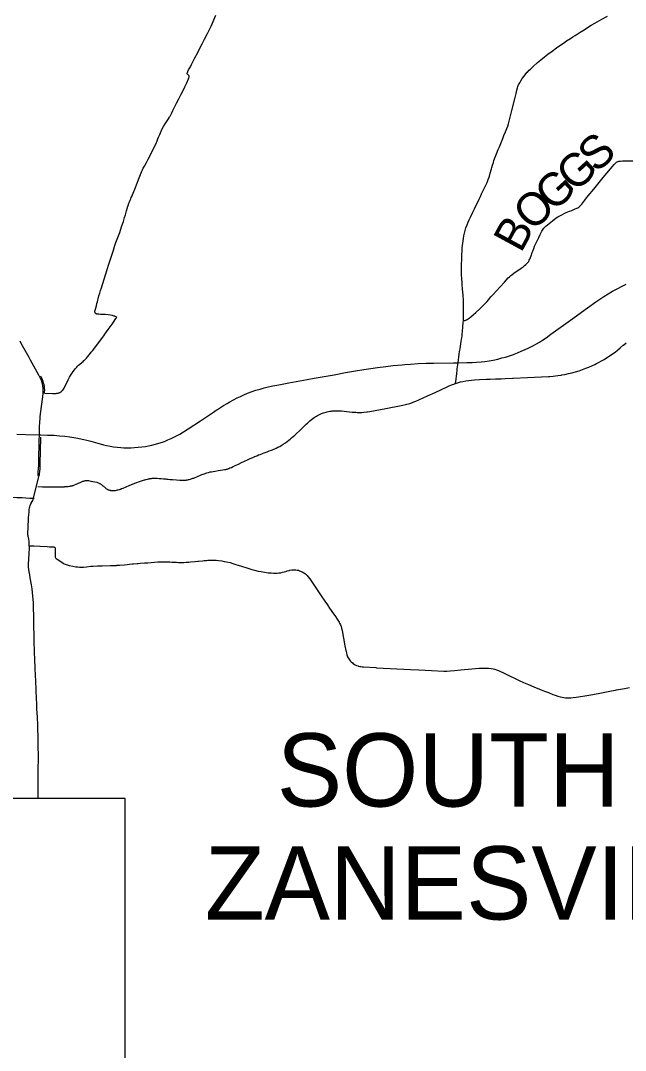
# Model space of a CAD drawing. Extents: x 1761803 to 2441803, y 509895 to 949895.
# Drawn here: x 2107842 to 2124353, y 786865 to 814988 of the extents above; entities that cross this region are included whole.
import ezdxf

# ---------------------------------------------------------------- set-up
doc = ezdxf.new("R2010")
doc.units = 0
for name, color, linetype in [('GM_X_County_Road', 7, 'Continuous'), ('GM_X_Minor_Lake', 7, 'Continuous'), ('GM_X_Minor_River', 7, 'Continuous'), ('GM_X_Minor_River_Text', 7, 'Continuous'), ('GM_X_State_Location', 7, 'Continuous')]:
    doc.layers.add(name, color=color, linetype=linetype)

msp = doc.modelspace()

# ---------------------------------------------------------------- linework, layer by layer
at = {"layer": 'GM_X_County_Road'}
for points in [[(2123340, 810199), (2123493, 810385), (2123751, 810703), (2124047, 811054), (2124099, 811111), (2124113, 811122), (2124127, 811131), (2124143, 811138), (2124158, 811143), (2124173, 811147), (2124189, 811150), (2124221, 811153), (2124270, 811156), (2124434, 811156), (2124926, 811161), (2125171, 811164), (2125433, 811164), (2125586, 811166)], [(2121823, 808691), (2121852, 808763), (2121875, 808824), (2121901, 808884), (2121931, 808952), (2121987, 809060), (2122030, 809149), (2122071, 809238), (2122087, 809266), (2122105, 809293), (2122125, 809318), (2122148, 809341), (2122185, 809374), (2122362, 809520), (2122466, 809598), (2122506, 809625), (2122562, 809658), (2122620, 809687), (2122679, 809716), (2122738, 809743), (2122828, 809782), (2122888, 809806), (2122964, 809837), (2123025, 809864), (2123054, 809879), (2123082, 809897), (2123103, 809912), (2123120, 809929), (2123146, 809955), (2123163, 809975), (2123189, 810009), (2123244, 810081), (2123296, 810145), (2123340, 810199)], [(2121505, 808228), (2121559, 808266), (2121601, 808296), (2121637, 808326), (2121672, 808360), (2121694, 808386), (2121713, 808412), (2121728, 808442), (2121742, 808472), (2121760, 808518), (2121778, 808564), (2121812, 808656), (2121823, 808691)], [(2119930, 806796), (2119956, 806799), (2119978, 806802), (2119984, 806804), (2120000, 806809), (2120016, 806816), (2120030, 806824), (2120059, 806841), (2120085, 806860), (2120137, 806901), (2120206, 806960), (2120274, 807019), (2120381, 807119), (2120576, 807317), (2120620, 807366), (2120684, 807441), (2120735, 807503), (2120835, 807609), (2120937, 807716), (2121053, 807846), (2121157, 807959), (2121191, 807994), (2121227, 808027), (2121252, 808048), (2121304, 808086), (2121505, 808228)]]:
    msp.add_lwpolyline(points, dxfattribs=at)
at = {"layer": 'GM_X_Minor_Lake'}
for points in [[(2112327, 813175), (2112381, 813289), (2112426, 813395), (2112437, 813426), (2112441, 813443), (2112443, 813460), (2112443, 813472), (2112441, 813481), (2112435, 813490), (2112427, 813498), (2112416, 813505), (2112405, 813515), (2112395, 813525), (2112390, 813534), (2112389, 813542), (2112390, 813552), (2112395, 813567), (2112407, 813596), (2112430, 813640), (2112476, 813727), (2112506, 813785), (2112602, 813975), (2112677, 814120), (2112744, 814252), (2112797, 814353), (2112866, 814483), (2112941, 814632), (2113007, 814760), (2113045, 814840), (2113176, 815132)], [(2121958, 813840), (2122042, 813912), (2122143, 813996), (2122235, 814067), (2122355, 814156), (2122474, 814244), (2122595, 814330), (2122662, 814375), (2122743, 814431), (2122853, 814502), (2122915, 814541), (2122978, 814581), (2123116, 814669), (2123227, 814740), (2123350, 814820), (2123420, 814864), (2123519, 814922), (2123706, 815024), (2123850, 815101), (2123866, 815110)], [(2120695, 810936), (2120707, 810975), (2120724, 811036), (2120748, 811115), (2120764, 811165), (2120794, 811256), (2120831, 811347), (2120880, 811469), (2120912, 811544), (2120931, 811590), (2120949, 811635), (2121004, 811772), (2121036, 811847), (2121081, 811952), (2121118, 812043), (2121140, 812105), (2121160, 812167), (2121183, 812246), (2121256, 812532), (2121332, 812849), (2121368, 812996), (2121391, 813090), (2121407, 813149), (2121417, 813184), (2121427, 813211), (2121439, 813235), (2121468, 813290), (2121502, 813346), (2121537, 813403), (2121586, 813470), (2121636, 813533), (2121676, 813580), (2121679, 813583), (2121724, 813632), (2121759, 813666), (2121832, 813733), (2121958, 813840)], [(2111923, 812379), (2111943, 812416), (2111969, 812470), (2111997, 812529), (2112100, 812733), (2112162, 812849), (2112230, 812980), (2112318, 813156), (2112327, 813175)], [(2111275, 811112), (2111323, 811201), (2111440, 811428), (2111499, 811546), (2111541, 811636), (2111571, 811703), (2111593, 811762), (2111608, 811803), (2111639, 811879), (2111678, 811969), (2111707, 812028), (2111746, 812099), (2111789, 812169), (2111861, 812279), (2111906, 812348), (2111918, 812370), (2111923, 812379)], [(2111133, 810828), (2111153, 810876), (2111171, 810915), (2111191, 810956), (2111221, 811013), (2111275, 811112)], [(2110764, 809895), (2110778, 809936), (2110801, 809999), (2110819, 810043), (2110836, 810087), (2110850, 810119), (2110865, 810156), (2110884, 810203), (2110895, 810230), (2110977, 810428), (2111007, 810505), (2111076, 810690), (2111133, 810828)], [(2119848, 806086), (2119862, 806174), (2119879, 806281), (2119887, 806329), (2119895, 806380), (2119896, 806388), (2119900, 806422), (2119908, 806497), (2119919, 806626), (2119927, 806741), (2119930, 806796), (2119934, 806844), (2119936, 806934), (2119938, 806986), (2119938, 807045), (2119938, 807113), (2119936, 807212), (2119930, 807344), (2119920, 807488), (2119907, 807656), (2119899, 807783), (2119893, 807867), (2119890, 807908), (2119880, 808071), (2119878, 808101), (2119876, 808156), (2119875, 808242), (2119877, 808342), (2119884, 808456), (2119892, 808607), (2119896, 808685), (2119898, 808733), (2119901, 808785), (2119905, 808844), (2119912, 808906), (2119921, 808970), (2119930, 809035), (2119946, 809114), (2119961, 809181), (2119982, 809260), (2120001, 809324), (2120034, 809415), (2120061, 809481), (2120091, 809547), (2120127, 809624), (2120191, 809757), (2120232, 809848), (2120361, 810111), (2120395, 810186), (2120428, 810256), (2120502, 810407), (2120544, 810496), (2120577, 810571), (2120607, 810647), (2120631, 810713), (2120640, 810740), (2120662, 810819), (2120695, 810936)], [(2110465, 806880), (2110445, 806896), (2110427, 806907), (2110413, 806913), (2110396, 806920), (2110373, 806927), (2110350, 806932), (2110299, 806942), (2110231, 806953), (2110155, 806962), (2110112, 806965), (2110071, 806965), (2110025, 806965), (2109974, 806967), (2109948, 806970), (2109936, 806972), (2109925, 806974), (2109916, 806977), (2109908, 806981), (2109895, 806988), (2109887, 806995), (2109882, 807002), (2109879, 807008), (2109877, 807019), (2109873, 807032), (2109872, 807044), (2109873, 807057), (2109881, 807084), (2109910, 807198), (2109925, 807260), (2109937, 807304), (2109949, 807351), (2109960, 807393), (2109981, 807470), (2110005, 807548), (2110025, 807613), (2110049, 807692), (2110122, 807926), (2110205, 808193), (2110250, 808334), (2110287, 808443), (2110335, 808583), (2110377, 808723), (2110407, 808817), (2110446, 808927), (2110549, 809204), (2110600, 809360), (2110648, 809505), (2110683, 809613), (2110703, 809686), (2110735, 809797), (2110761, 809884), (2110764, 809895)], [(2109571, 805704), (2109575, 805708), (2109621, 805750), (2109639, 805770), (2109667, 805802), (2109719, 805866), (2109769, 805931), (2109801, 805972), (2110088, 806347), (2110113, 806380), (2110144, 806422), (2110234, 806552), (2110339, 806698), (2110374, 806749), (2110446, 806854), (2110465, 806880)], [(2108331, 802551), (2108325, 802568), (2108323, 802575), (2108322, 802579), (2108319, 802591), (2108319, 802604), (2108324, 802662), (2108331, 802752), (2108336, 802842), (2108337, 802887), (2108337, 802908), (2108344, 803166), (2108344, 803185), (2108347, 803297), (2108350, 803431), (2108352, 803484), (2108353, 803555), (2108355, 803633), (2108356, 803677), (2108357, 803717), (2108357, 803729), (2108358, 803769), (2108359, 803794), (2108361, 803900), (2108366, 804016), (2108375, 804130), (2108377, 804143), (2108380, 804171), (2108389, 804245), (2108445, 804715), (2108454, 804816), (2108457, 804879), (2108457, 804929), (2108454, 804965), (2108450, 804999), (2108446, 805027), (2108439, 805056), (2108430, 805092), (2108418, 805138), (2108408, 805163), (2108395, 805198), (2108380, 805229), (2108342, 805302), (2108205, 805555), (2108115, 805716), (2108074, 805789), (2107861, 806174), (2107827, 806234)], [(2119762, 805460), (2119765, 805481), (2119772, 805533), (2119786, 805645), (2119817, 805882), (2119827, 805950), (2119839, 806028), (2119848, 806086)], [(2108810, 804807), (2108833, 804809), (2108850, 804811), (2108866, 804815), (2108883, 804820), (2108898, 804826), (2108913, 804833), (2108942, 804851), (2108956, 804860), (2108969, 804871), (2108981, 804883), (2108993, 804895), (2109013, 804921), (2109031, 804950), (2109054, 804994), (2109102, 805099), (2109140, 805176), (2109178, 805247), (2109221, 805320), (2109255, 805374), (2109300, 805439), (2109340, 805491), (2109373, 805528), (2109395, 805551), (2109425, 805578), (2109456, 805605), (2109512, 805651), (2109547, 805682), (2109571, 805704)], [(2119719, 805081), (2119733, 805197), (2119742, 805287), (2119747, 805329), (2119762, 805460)], [(2108495, 804814), (2108497, 804847), (2108499, 804896), (2108496, 804945), (2108491, 804993), (2108482, 805041), (2108471, 805089), (2108456, 805135), (2108438, 805181), (2108418, 805225), (2108390, 805276)], [(2108495, 804814), (2108717, 804807), (2108768, 804807), (2108800, 804807), (2108810, 804807)], [(2108331, 802551), (2108345, 802566), (2108353, 802574), (2108357, 802582), (2108361, 802591), (2108362, 802600), (2108368, 802673), (2108372, 802752), (2108377, 802883), (2108378, 802908), (2108379, 802980), (2108383, 803159), (2108384, 803175), (2108386, 803300), (2108387, 803344), (2108390, 803480), (2108390, 803499), (2108390, 803543), (2108392, 803613)], [(2108079, 800647), (2108079, 800686), (2108076, 800739), (2108072, 800775), (2108064, 800823), (2108048, 800904), (2108045, 800925), (2108043, 800940), (2108041, 800954), (2108040, 800970), (2108039, 801020), (2108044, 801119), (2108062, 801415), (2108072, 801564), (2108078, 801630), (2108086, 801679), (2108094, 801711), (2108104, 801743), (2108123, 801789), (2108136, 801817), (2108142, 801829), (2108155, 801853), (2108173, 801885), (2108345, 802566)], [(2108057, 800097), (2108055, 800130), (2108056, 800162), (2108063, 800265), (2108064, 800286), (2108072, 800425), (2108082, 800591), (2108083, 800611), (2108079, 800647)], [(2108079, 800647), (2108207, 800641), (2108370, 800633), (2108374, 800633), (2108566, 800623), (2108631, 800620), (2108735, 800617), (2108748, 800615), (2108762, 800610), (2108770, 800606), (2108777, 800602)], [(2108777, 800602), (2108784, 800589), (2108788, 800577), (2108789, 800558), (2108789, 800529), (2108783, 800398), (2108783, 800393), (2108783, 800376), (2108782, 800367), (2108782, 800360), (2108782, 800350), (2108786, 800335), (2108793, 800321), (2108802, 800309), (2108814, 800299), (2108841, 800280), (2108936, 800216), (2109005, 800171), (2109033, 800155), (2109063, 800143), (2109109, 800127), (2109172, 800109), (2109268, 800088), (2109349, 800074), (2109397, 800067), (2109446, 800064), (2109495, 800064), (2109561, 800066), (2109642, 800074), (2109756, 800087), (2109783, 800090), (2109822, 800092), (2109937, 800096), (2110072, 800100), (2110298, 800106), (2110397, 800108), (2110462, 800111), (2110473, 800112), (2110544, 800117), (2110675, 800129), (2110887, 800149), (2110921, 800152), (2111025, 800161), (2111052, 800163), (2111105, 800167)], [(2108196, 798947), (2108195, 798992), (2108192, 799090), (2108186, 799188), (2108179, 799270), (2108169, 799368), (2108156, 799466), (2108139, 799579), (2108107, 799772), (2108093, 799851), (2108079, 799932), (2108061, 800062), (2108057, 800088), (2108057, 800097)], [(2111105, 800167), (2111224, 800177), (2111311, 800183), (2111409, 800191), (2111588, 800205), (2111670, 800209), (2111785, 800209), (2111916, 800205), (2111969, 800202), (2112042, 800197), (2112095, 800194), (2112151, 800191)], [(2112151, 800191), (2112159, 800191), (2112185, 800190), (2112224, 800190), (2112294, 800192), (2112366, 800196), (2112381, 800197), (2112435, 800202), (2112483, 800207), (2112597, 800217), (2112677, 800225), (2112702, 800227), (2112806, 800237), (2112852, 800241), (2112921, 800248), (2112951, 800249), (2112992, 800250)], [(2112992, 800250), (2113002, 800250), (2113031, 800250), (2113089, 800252), (2113136, 800250), (2113181, 800249), (2113245, 800244), (2113335, 800231), (2113401, 800221), (2113465, 800209), (2113561, 800185), (2113639, 800162), (2113717, 800137), (2113872, 800086), (2114043, 800030), (2114153, 799998), (2114232, 799978), (2114328, 799956), (2114408, 799940), (2114505, 799924), (2114602, 799911), (2114633, 799908)], [(2114633, 799908), (2114684, 799903), (2114749, 799898), (2114798, 799897), (2114846, 799899), (2114895, 799904), (2114944, 799911), (2114992, 799921), (2115039, 799933), (2115070, 799942), (2115086, 799947), (2115116, 799958), (2115163, 799973), (2115171, 799974), (2115196, 799980), (2115245, 799987), (2115294, 799991), (2115327, 799991), (2115360, 799989), (2115393, 799984), (2115426, 799976), (2115457, 799966), (2115479, 799957)], [(2115479, 799957), (2115503, 799947), (2115533, 799933), (2115576, 799908), (2115616, 799879), (2115642, 799858), (2115666, 799835), (2115687, 799809), (2115735, 799743), (2115921, 799473), (2115922, 799472)], [(2115922, 799472), (2116050, 799283), (2116150, 799134), (2116216, 799036), (2116246, 798992)], [(2116246, 798992), (2116260, 798971), (2116343, 798849), (2116436, 798714), (2116483, 798646), (2116535, 798563), (2116552, 798534), (2116573, 798489), (2116590, 798443), (2116605, 798395), (2116620, 798331), (2116698, 797912), (2116721, 797783), (2116726, 797762), (2116735, 797719), (2116748, 797672), (2116758, 797641), (2116771, 797611), (2116785, 797583), (2116802, 797555), (2116821, 797529), (2116842, 797503), (2116864, 797480), (2116899, 797446), (2116924, 797426), (2116951, 797409), (2116980, 797394), (2117010, 797380), (2117025, 797375), (2117055, 797365), (2117071, 797361), (2117101, 797353), (2117132, 797348), (2117163, 797344), (2117202, 797338), (2117537, 797318), (2117538, 797318)], [(2108323, 793748), (2108323, 793801), (2108322, 793947), (2108322, 794144), (2108322, 794258), (2108322, 794373), (2108323, 794488), (2108325, 794619), (2108327, 794767), (2108330, 794872), (2108328, 794987), (2108326, 795095), (2108323, 795275), (2108321, 795406), (2108318, 795505), (2108316, 795587), (2108312, 795703), (2108311, 795751), (2108300, 795969), (2108289, 796192), (2108283, 796339), (2108277, 796470), (2108267, 796700), (2108255, 796978), (2108250, 797088), (2108238, 797322), (2108233, 797535), (2108225, 797749), (2108221, 797831), (2108215, 797961), (2108212, 798059), (2108209, 798207), (2108208, 798289), (2108206, 798368), (2108205, 798436), (2108204, 798501), (2108201, 798631), (2108201, 798713), (2108199, 798779), (2108198, 798894), (2108196, 798947)], [(2117538, 797318), (2117554, 797317), (2118489, 797270), (2118718, 797257), (2119061, 797237), (2119398, 797224), (2119482, 797224), (2119570, 797228), (2119688, 797237), (2119863, 797254), (2120365, 797301), (2120460, 797305), (2120533, 797308), (2120614, 797305), (2120693, 797297), (2120739, 797287), (2120782, 797275), (2120787, 797274), (2120830, 797261), (2120887, 797240), (2121061, 797157), (2121455, 796963), (2121576, 796908), (2121704, 796855), (2121856, 796794), (2122054, 796714), (2122146, 796679), (2122252, 796637), (2122374, 796588), (2122435, 796565), (2122513, 796539), (2122576, 796521), (2122623, 796510), (2122671, 796502), (2122720, 796496), (2122769, 796492), (2122818, 796491), (2122867, 796492), (2122932, 796498), (2123013, 796508), (2123077, 796519), (2123303, 796559), (2123464, 796589), (2123704, 796634), (2123978, 796685), (2124084, 796705), (2124107, 796710), (2124220, 796731), (2124332, 796752), (2124462, 796776)]]:
    msp.add_lwpolyline(points, dxfattribs=at)
at = {"layer": 'GM_X_Minor_River'}
msp.add_lwpolyline([(2107742, 803691), (2107986, 803684), (2108356, 803677), (2108363, 803677), (2108394, 803676), (2108577, 803671), (2108758, 803662), (2108905, 803652), (2109052, 803638), (2109182, 803622), (2109296, 803605), (2109408, 803584), (2109521, 803560), (2109571, 803548), (2109648, 803530), (2109759, 803501), (2110012, 803428), (2110107, 803404), (2110188, 803386), (2110284, 803367), (2110382, 803351), (2110480, 803339), (2110578, 803329), (2110660, 803325), (2110759, 803322), (2110833, 803323), (2110857, 803323), (2110956, 803328), (2111054, 803336), (2111152, 803346), (2111250, 803361), (2111331, 803375), (2111427, 803396), (2111523, 803420), (2111618, 803448), (2111712, 803478), (2111789, 803506), (2111865, 803537), (2111956, 803577), (2112045, 803619), (2112118, 803657), (2112190, 803697), (2112288, 803756), (2112413, 803835), (2112756, 804061), (2112865, 804133), (2112975, 804206), (2113109, 804295), (2113183, 804345), (2113220, 804369), (2113382, 804474), (2113480, 804534), (2113551, 804575), (2113651, 804630), (2113753, 804683), (2113842, 804726), (2113932, 804765), (2114038, 804809), (2114160, 804855), (2114268, 804893), (2114378, 804927), (2114488, 804958), (2114600, 804985), (2114728, 805013), (2114889, 805044), (2115163, 805094), (2115664, 805184), (2115857, 805219), (2116406, 805318), (2116713, 805374), (2116987, 805423), (2117214, 805461), (2117408, 805491), (2117587, 805516), (2117815, 805545), (2118010, 805566), (2118255, 805589), (2118329, 805595), (2118484, 805607), (2118697, 805620), (2118910, 805631), (2119123, 805636), (2119664, 805644), (2119786, 805645), (2120025, 805648), (2120173, 805653), (2120288, 805659), (2120419, 805670), (2120517, 805682), (2120630, 805699), (2120743, 805719), (2120872, 805746), (2120984, 805774), (2121079, 805800), (2121188, 805835), (2121297, 805872), (2121319, 805880), (2121405, 805913), (2121511, 805956), (2121616, 806002), (2121720, 806051), (2121823, 806103), (2121924, 806159), (2122008, 806209), (2122092, 806262), (2122187, 806326), (2122321, 806421), (2122852, 806808), (2123316, 807145), (2123543, 807308), (2123651, 807382), (2123761, 807453), (2123887, 807530), (2124000, 807595), (2124130, 807666), (2124261, 807734), (2124378, 807792)], dxfattribs=at)
at = {"layer": 'GM_X_Minor_River_Text'}
for points in [[(2119719, 805081), (2119851, 805120), (2119914, 805135), (2119994, 805149), (2120075, 805160), (2120156, 805168), (2120238, 805175), (2120369, 805184), (2120565, 805192), (2120663, 805196), (2120811, 805201), (2120958, 805208), (2121072, 805212), (2121268, 805222), (2121287, 805223), (2121678, 805239), (2122061, 805255), (2122255, 805268), (2122294, 805271), (2122377, 805278), (2122507, 805294), (2122604, 805308), (2122618, 805311), (2122701, 805326), (2122798, 805347), (2122893, 805370), (2122995, 805398), (2123089, 805425), (2123182, 805460), (2123276, 805495), (2123356, 805527), (2123437, 805561), (2123517, 805598), (2123563, 805621), (2123569, 805624), (2123641, 805662), (2123699, 805693), (2123770, 805734), (2123840, 805777), (2123909, 805821), (2123977, 805867), (2124070, 805934), (2124135, 805985), (2124211, 806047), (2124296, 806120), (2124298, 806122), (2124373, 806186)], [(2113685, 802827), (2113700, 802834), (2113788, 802875), (2113876, 802916), (2113954, 802954), (2114032, 802990), (2114113, 803026), (2114185, 803058), (2114234, 803081), (2114295, 803106), (2114340, 803125), (2114344, 803126), (2114386, 803143), (2114425, 803158), (2114462, 803172), (2114573, 803215), (2114630, 803235), (2114689, 803257), (2114723, 803270), (2114815, 803309), (2114867, 803335), (2114916, 803361), (2114953, 803382), (2115013, 803420), (2115071, 803459), (2115121, 803494), (2115169, 803531), (2115201, 803557), (2115240, 803591), (2115325, 803666), (2115498, 803832), (2115639, 803968), (2115670, 803998), (2115739, 804059), (2115784, 804096), (2115819, 804123), (2115853, 804146), (2115885, 804166), (2115918, 804186), (2115948, 804203), (2115980, 804220), (2116017, 804237), (2116061, 804255), (2116112, 804274), (2116147, 804285), (2116181, 804294), (2116212, 804303), (2116247, 804311), (2116280, 804318), (2116319, 804325), (2116349, 804329), (2116366, 804329), (2116413, 804333), (2116445, 804334), (2116472, 804334), (2116505, 804333), (2116571, 804330), (2116586, 804329), (2116604, 804328), (2116891, 804298), (2116995, 804291), (2117031, 804289), (2117063, 804287), (2117086, 804287), (2117120, 804287), (2117160, 804290), (2117216, 804295), (2117296, 804305), (2117310, 804307), (2117376, 804316), (2117811, 804395), (2118229, 804473), (2118280, 804484), (2118357, 804502), (2118387, 804509), (2118436, 804523), (2118467, 804534), (2118539, 804558), (2118578, 804573), (2118631, 804595), (2118710, 804630), (2118948, 804739), (2119156, 804835), (2119510, 804996), (2119543, 805011), (2119589, 805031), (2119636, 805050), (2119667, 805062), (2119689, 805071), (2119719, 805081)], [(2111626, 802485), (2111677, 802482), (2111740, 802478), (2111760, 802476), (2111782, 802474), (2111806, 802471), (2111835, 802468), (2111873, 802465), (2111923, 802460), (2111988, 802454), (2112096, 802444), (2112185, 802438), (2112236, 802435), (2112279, 802434), (2112317, 802436), (2112338, 802437), (2112360, 802440), (2112380, 802443), (2112405, 802448), (2112427, 802453), (2112445, 802458), (2112480, 802468), (2112547, 802488), (2112570, 802496), (2112589, 802504), (2112755, 802574), (2112789, 802589), (2112830, 802605), (2112852, 802613), (2112879, 802624), (2112902, 802631), (2112922, 802637), (2112973, 802651), (2113020, 802662), (2113055, 802669), (2113097, 802677), (2113151, 802686), (2113236, 802699), (2113363, 802718), (2113405, 802725), (2113420, 802728), (2113443, 802732), (2113461, 802736), (2113479, 802740), (2113498, 802747), (2113507, 802750)], [(2113507, 802750), (2113517, 802753), (2113531, 802759), (2113558, 802770), (2113599, 802787), (2113649, 802810), (2113685, 802827)], [(2108314, 802264), (2108443, 802256), (2108482, 802256), (2108658, 802255), (2108842, 802256), (2108945, 802257), (2108955, 802257), (2108986, 802258), (2109013, 802259), (2109036, 802260), (2109053, 802261), (2109074, 802263), (2109093, 802265), (2109115, 802266), (2109140, 802269), (2109173, 802273), (2109192, 802276), (2109208, 802279), (2109227, 802283), (2109248, 802287), (2109263, 802291), (2109278, 802295), (2109291, 802300), (2109312, 802308), (2109363, 802330), (2109483, 802384), (2109527, 802400), (2109544, 802406), (2109562, 802412), (2109577, 802417), (2109593, 802421)], [(2109593, 802421), (2109611, 802425), (2109624, 802426), (2109643, 802428), (2109663, 802427), (2109693, 802424), (2109758, 802414), (2109761, 802414), (2109810, 802404), (2109868, 802392), (2109919, 802380), (2109940, 802373), (2109969, 802361), (2109982, 802354), (2109994, 802349), (2110004, 802343), (2110020, 802335)], [(2110020, 802335), (2110033, 802327), (2110048, 802316), (2110060, 802308), (2110072, 802300), (2110081, 802293), (2110088, 802287), (2110104, 802273), (2110119, 802260), (2110138, 802242), (2110156, 802227), (2110173, 802214), (2110193, 802200), (2110221, 802184), (2110234, 802177), (2110251, 802170), (2110268, 802165), (2110283, 802161), (2110297, 802158), (2110313, 802156), (2110332, 802155), (2110355, 802154), (2110391, 802155), (2110411, 802156), (2110430, 802159), (2110458, 802164), (2110484, 802170), (2110508, 802176), (2110542, 802186), (2110565, 802194), (2110600, 802206), (2110639, 802220), (2110804, 802288), (2110965, 802354)], [(2110965, 802354), (2111016, 802375), (2111061, 802393), (2111111, 802411), (2111222, 802444), (2111242, 802449), (2111264, 802455), (2111305, 802465), (2111332, 802471), (2111362, 802478), (2111372, 802479), (2111383, 802481), (2111400, 802484), (2111415, 802486), (2111430, 802488), (2111446, 802489), (2111462, 802490), (2111485, 802489), (2111510, 802489), (2111569, 802488), (2111626, 802485)], [(2107585, 801977), (2107737, 801967), (2107888, 801960), (2107985, 801956), (2108097, 801949), (2108208, 801943)]]:
    msp.add_lwpolyline(points, dxfattribs=at)
at = {"layer": 'GM_X_State_Location'}
msp.add_lwpolyline([(2081320, 778913), (2110696, 778913), (2110696, 793748), (2081320, 793748)], close=True, dxfattribs=at)

# ---------------------------------------------------------------- texts
at = {"layer": 'GM_X_County_Road'}
for s, height, rotation, p in [('S', 900, 42.2617, (2123562, 810806)), ('G', 900, 42.2624, (2122976, 810273)), ('G', 900, 42.2582, (2122390, 809741)), ('O', 900, 42.495, (2121807, 809206)), ('B', 900, 61.4991, (2121502, 808618)), ('SOUTH', 2000, 0, (2114836, 793525)), ('ZANESVILLE', 2000, 0, (2112870, 790440))]:
    msp.add_text(s, height=height, rotation=rotation, dxfattribs=at).set_placement(p)

doc.saveas('drawing.dxf')
